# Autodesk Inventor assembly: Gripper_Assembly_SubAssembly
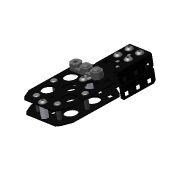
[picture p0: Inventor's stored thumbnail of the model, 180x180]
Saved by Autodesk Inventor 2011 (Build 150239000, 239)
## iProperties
Created: 2007-10
Part Number: Gripper_Assembly_SubAssembly
Document SubType Name: Assembly
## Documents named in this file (8)
- C:\Data Folder\VEX 2011\Inventor Datasets\Unit 12\Gripper_Assembly_SubAssembly.iam
- C:\Data Folder\VEX 2011\Inventor Datasets\Unit 12\Components\BEARING-FLAT.ipt
- C:\Data Folder\VEX 2011\Inventor Datasets\Unit 12\Components\Vexplorer-Claw-Brk RevA.ipt
- C:\Data Folder\VEX 2011\Inventor Datasets\Unit 12\Components\SCREW-832_SBS0832-0250ZB.ipt
- C:\Data Folder\VEX 2011\Inventor Datasets\Unit 12\Components\Vexplorer-Claw-Pin.iam
- C:\Data Folder\VEX 2011\Inventor Datasets\Unit 12\Components\BEAM-0500.ipt
- C:\Data Folder\VEX 2011\Inventor Datasets\Unit 12\Components\BEARING-RIVET.ipt
- C:\Data Folder\VEX 2011\Inventor Datasets\Unit 12\Components\WASHER-TEFLON.ipt
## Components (25 placed, 7 different names)
1. BEARING-FLAT — Mate:40, Mate:41, Mate:42, Insert:1, Insert:2
2. Vexplorer-Claw-Brk RevA — Mate:1, Mate:2, Mate:3, Mate:4, Mate:5, Mate:6, Mate:7, Mate:8, Mate:9, Mate:10, Mate:12, Mate:14, Mate:15, Mate:17, Mate:18, Mate:19, Mate:21, Mate:22, Mate:23, Mate:25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
3. SCREW-832_SBS0832-0250ZB — Mate:14, Mate:15, Mate:16
4. Vexplorer-Claw-Brk RevA — Mate:34, Mate:35, Mate:36, Mate:37, Mate:39, Flush:3, Mate:60, Mate:71
5. SCREW-832_SBS0832-0250ZB — Mate:22, Mate:23, Mate:24
6. Vexplorer-Claw-Pin [sub-assembly] — Mate:7, Mate:8
7. SCREW-832_SBS0832-0250ZB — Mate:18, Mate:19, Mate:20
8. BEAM-0500 — Mate:20, Mate:21
9. Vexplorer-Claw-Pin [sub-assembly] — Mate:5, Mate:6
10. BEAM-0500 — Mate:24, Mate:25
11. BEAM-0500 — Mate:32, Mate:33, Mate:36, Mate:38
12. SCREW-832_SBS0832-0250ZB — Mate:38, Mate:39
13. SCREW-832_SBS0832-0250ZB — Mate:13, Mate:37
14. SCREW-832_SBS0832-0250ZB — Mate:30, Mate:31, Mate:32
15. BEAM-0500 — Mate:11, Mate:12, Mate:13, Mate:34, Mate:35
16. SCREW-832_SBS0832-0250ZB — Mate:26, Mate:27, Mate:28
17. BEAM-0500 — Mate:16, Mate:17
18. SCREW-832_SBS0832-0250ZB — Mate:9, Mate:10, Mate:11
19. Vexplorer-Claw-Pin [sub-assembly] — Mate:3, Mate:4
20. BEARING-RIVET — Insert:1
21. WASHER-TEFLON
22. WASHER-TEFLON — Mate:71
23. BEARING-RIVET — Insert:2
24. Vexplorer-Claw-Pin [sub-assembly] — Mate:1, Mate:2
25. BEAM-0500 — Mate:28, Mate:29
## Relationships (50: Mate 45, Insert 2, Flush 2, Angle 1)
- Mate:1: Vexplorer-Claw-Brk RevA ↔ Vexplorer-Claw-Pin
- Mate:2: Vexplorer-Claw-Brk RevA ↔ Vexplorer-Claw-Pin
- Mate:3: Vexplorer-Claw-Brk RevA ↔ Vexplorer-Claw-Pin
- Mate:4: Vexplorer-Claw-Brk RevA ↔ Vexplorer-Claw-Pin
- Mate:5: Vexplorer-Claw-Brk RevA ↔ Vexplorer-Claw-Pin
- Mate:6: Vexplorer-Claw-Brk RevA ↔ Vexplorer-Claw-Pin
- Mate:7: Vexplorer-Claw-Brk RevA ↔ Vexplorer-Claw-Pin
- Mate:8: Vexplorer-Claw-Brk RevA ↔ Vexplorer-Claw-Pin
- Mate:9: Vexplorer-Claw-Brk RevA ↔ SCREW-832_SBS0832-0250ZB
- Mate:10: Vexplorer-Claw-Brk RevA ↔ SCREW-832_SBS0832-0250ZB
- Mate:11: BEAM-0500 ↔ SCREW-832_SBS0832-0250ZB
- Mate:12: Vexplorer-Claw-Brk RevA ↔ BEAM-0500
- Mate:13: SCREW-832_SBS0832-0250ZB ↔ BEAM-0500
- Mate:14: Vexplorer-Claw-Brk RevA ↔ SCREW-832_SBS0832-0250ZB
- Mate:15: Vexplorer-Claw-Brk RevA ↔ SCREW-832_SBS0832-0250ZB
- Mate:16: SCREW-832_SBS0832-0250ZB ↔ BEAM-0500
- Mate:17: Vexplorer-Claw-Brk RevA ↔ BEAM-0500
- Mate:18: Vexplorer-Claw-Brk RevA ↔ SCREW-832_SBS0832-0250ZB
- Mate:19: Vexplorer-Claw-Brk RevA ↔ SCREW-832_SBS0832-0250ZB
- Mate:20: SCREW-832_SBS0832-0250ZB ↔ BEAM-0500
- Mate:21: Vexplorer-Claw-Brk RevA ↔ BEAM-0500
- Mate:22: Vexplorer-Claw-Brk RevA ↔ SCREW-832_SBS0832-0250ZB
- Mate:23: Vexplorer-Claw-Brk RevA ↔ SCREW-832_SBS0832-0250ZB
- Mate:24: SCREW-832_SBS0832-0250ZB ↔ BEAM-0500
- Mate:25: Vexplorer-Claw-Brk RevA ↔ BEAM-0500
- Mate:26: Vexplorer-Claw-Brk RevA ↔ SCREW-832_SBS0832-0250ZB
- Mate:27: Vexplorer-Claw-Brk RevA ↔ SCREW-832_SBS0832-0250ZB
- Mate:28: SCREW-832_SBS0832-0250ZB ↔ BEAM-0500
- Mate:29: Vexplorer-Claw-Brk RevA ↔ BEAM-0500
- Mate:30: Vexplorer-Claw-Brk RevA ↔ SCREW-832_SBS0832-0250ZB
- Mate:31: Vexplorer-Claw-Brk RevA ↔ SCREW-832_SBS0832-0250ZB
- Mate:32: BEAM-0500 ↔ SCREW-832_SBS0832-0250ZB
- Mate:33: Vexplorer-Claw-Brk RevA ↔ BEAM-0500
- Mate:34: Vexplorer-Claw-Brk RevA ↔ BEAM-0500
- Mate:35: Vexplorer-Claw-Brk RevA ↔ BEAM-0500
- Mate:36: Vexplorer-Claw-Brk RevA ↔ BEAM-0500
- Mate:37: Vexplorer-Claw-Brk RevA ↔ SCREW-832_SBS0832-0250ZB
- Mate:38: BEAM-0500 ↔ SCREW-832_SBS0832-0250ZB
- Mate:39: Vexplorer-Claw-Brk RevA ↔ SCREW-832_SBS0832-0250ZB
- Mate:40: BEARING-FLAT ↔ Vexplorer-Claw-Brk RevA
- Mate:41: BEARING-FLAT ↔ Vexplorer-Claw-Brk RevA
- Mate:42: BEARING-FLAT ↔ Vexplorer-Claw-Brk RevA
- Insert:1: BEARING-FLAT ↔ BEARING-RIVET
- Insert:2: BEARING-FLAT ↔ BEARING-RIVET
- Flush:3: Vexplorer-Claw-Brk RevA
- Mate:60: Vexplorer-Claw-Brk RevA
- Mate:71: Vexplorer-Claw-Brk RevA ↔ WASHER-TEFLON
- Mate:72: Vexplorer-Claw-Brk RevA
- Angle:1: Vexplorer-Claw-Brk RevA
- Flush:4: Vexplorer-Claw-Brk RevA
